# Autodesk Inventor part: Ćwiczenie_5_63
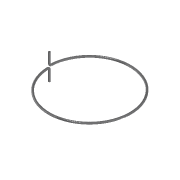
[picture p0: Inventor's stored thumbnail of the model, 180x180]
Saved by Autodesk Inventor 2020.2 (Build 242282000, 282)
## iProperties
Created: 2005-06
Part Number: Ćwiczenie_5_63
Document SubType Name: Modeling
Designer: F.Stasiak
Manufacturer: Standard
Standards Organization: Custom
Density: 1 g/cm^3
Material: Ogólny
Appearance: Chrom
Manager: www.cadconsulting.pl
Company: Fabian Stasiak CAD Consulting
Author: F.Stasiak
Subject: Zbiór ćwiczeń. Autodesk Inventor 2020. Kurs podstawowy
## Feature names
1. Przeciągnięcie1
2. Przeciągnięcie2
3. Zwój1
4. Wyciągnięcie złożone1
## Parameters: d1 = 3 mm, d2 = 3 mm, d3 = 15 mm, d4 = 15 mm, d5 = 3 mm, d6 = 0, d7 = 3 mm, d8 = 0, d9 = 0, d10 = 0, d11 = 4 mm, d12 = 4 mm, d13 = 2 mm, d15 = 9.83 mm, d16 = 0, d17 = 90 deg, d18 = 90 deg, d19 = 0, d20 = 0, d21 = 0, d22 = 90 deg, d23 = 0, d24 = 90 deg, d25 = 0, d26 = 0
